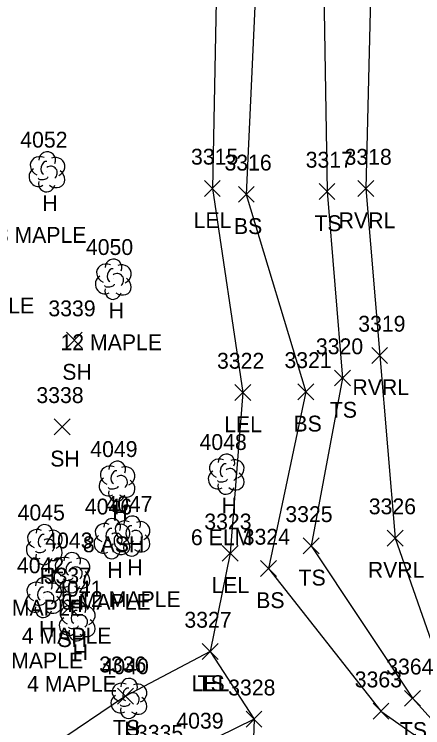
# Model space of a CAD drawing. Extents: x 1461855 to 1464118, y 556196 to 557441.
# Drawn here: x 1462006.8 to 1462058.2, y 556619.2 to 556709.1 of the extents above; entities that cross this region are included whole.
import ezdxf

# ---------------------------------------------------------------- set-up
doc = ezdxf.new("R2010")
doc.units = 0
for name, color, linetype in [('L_A', 7, 'Continuous'), ('L_C', 7, 'Continuous'), ('L_I', 7, 'Continuous'), ('L_TIC', 7, 'Continuous'), ('LARO', 7, 'Continuous'), ('LAWE', 7, 'Continuous'), ('LELB', 7, 'Continuous'), ('LTD', 7, 'Continuous')]:
    doc.layers.add(name, color=color, linetype=linetype)

msp = doc.modelspace()

# ---------------------------------------------------------------- linework, layer by layer
at = {"layer": 'L_TIC'}
for points in [[(1462030.75, 556686.131), (1462032.75, 556688.131)], [(1462032.75, 556686.131), (1462030.75, 556688.131)], [(1462035.024, 556685.385), (1462037.024, 556687.385)], [(1462037.024, 556685.385), (1462035.024, 556687.385)], [(1462045.194, 556685.747), (1462047.194, 556687.747)], [(1462047.194, 556685.747), (1462045.194, 556687.747)], [(1462045.194, 556685.747), (1462047.194, 556687.747)], [(1462047.194, 556685.747), (1462045.194, 556687.747)], [(1462050.091, 556686.112), (1462052.091, 556688.112)], [(1462052.091, 556686.112), (1462050.091, 556688.112)], [(1462013.361, 556667.016), (1462015.361, 556669.016)], [(1462015.361, 556667.016), (1462013.361, 556669.016)], [(1462051.825, 556665.076), (1462053.825, 556667.076)], [(1462053.825, 556665.076), (1462051.825, 556667.076)], [(1462047.138, 556662.233), (1462049.138, 556664.233)], [(1462049.138, 556662.233), (1462047.138, 556664.233)], [(1462034.594, 556660.411), (1462036.594, 556662.411)], [(1462036.594, 556660.411), (1462034.594, 556662.411)], [(1462042.522, 556660.49), (1462044.522, 556662.49)], [(1462044.522, 556660.49), (1462042.522, 556662.49)], [(1462011.842, 556656.082), (1462013.842, 556658.082)], [(1462013.842, 556656.082), (1462011.842, 556658.082)], [(1462053.764, 556642.062), (1462055.764, 556644.062)], [(1462055.764, 556642.062), (1462053.764, 556644.062)], [(1462043.201, 556641.081), (1462045.201, 556643.081)], [(1462045.201, 556641.081), (1462043.201, 556643.081)], [(1462032.996, 556640.147), (1462034.996, 556642.147)], [(1462034.996, 556640.147), (1462032.996, 556642.147)], [(1462037.833, 556638.233), (1462039.833, 556640.233)], [(1462039.833, 556638.233), (1462037.833, 556640.233)], [(1462012.766, 556633.331), (1462014.766, 556635.331)], [(1462014.766, 556633.331), (1462012.766, 556635.331)], [(1462030.483, 556627.768), (1462032.483, 556629.768)], [(1462032.483, 556627.768), (1462030.483, 556629.768)], [(1462030.483, 556627.768), (1462032.483, 556629.768)], [(1462032.483, 556627.768), (1462030.483, 556629.768)], [(1462019.803, 556622.137), (1462021.803, 556624.137)], [(1462021.803, 556622.137), (1462019.803, 556624.137)], [(1462055.957, 556621.87), (1462057.957, 556623.87)], [(1462057.957, 556621.87), (1462055.957, 556623.87)], [(1462051.988, 556620.249), (1462053.988, 556622.249)], [(1462053.988, 556620.249), (1462051.988, 556622.249)], [(1462036, 556619.231), (1462038, 556621.231)], [(1462038, 556619.231), (1462036, 556621.231)], [(1462036, 556619.231), (1462038, 556621.231)], [(1462038, 556619.231), (1462036, 556621.231)]]:
    msp.add_lwpolyline(points, dxfattribs=at)
at = {"layer": 'LARO'}
msp.add_lwpolyline([(1462028.293, 556804.845), (1462029.856, 556786.264), (1462034.967, 556768.458), (1462036.472, 556762.979), (1462033.427, 556748.898), (1462029.252, 556744.558), (1462032.364, 556727.057), (1462032.403, 556719.386), (1462031.75, 556687.131), (1462035.594, 556661.411), (1462033.996, 556641.147), (1462031.483, 556628.768), (1462037, 556620.231), (1462036.776, 556613.093), (1462055.688, 556606.979), (1462067.548, 556606.631), (1462078.525, 556595.396), (1462093.66, 556580.158), (1462100.331, 556564.645), (1462103.465, 556550.963), (1462104.582, 556534.352), (1462113.504, 556526.22)], dxfattribs=at)
at = {"layer": 'LAWE'}
msp.add_lwpolyline([(1462035.855, 556809.685), (1462040.285, 556805.29), (1462046.447, 556786.582), (1462047.954, 556769.867), (1462051.587, 556748.694), (1462051.929, 556721.581), (1462051.091, 556687.112), (1462052.825, 556666.076), (1462054.764, 556643.062), (1462061.562, 556623.629), (1462070.818, 556617.59), (1462084.777, 556608.704), (1462105.974, 556601.343), (1462119.177, 556579.727), (1462124.613, 556564.474), (1462124.915, 556535.352)], dxfattribs=at)
at = {"layer": 'LELB'}
for points in [[(1462040.285, 556805.29), (1462040.375, 556785.854), (1462042.823, 556769.757), (1462047.844, 556748.135), (1462045.64, 556722.171), (1462046.194, 556686.747)], [(1462033.427, 556748.898), (1462037.255, 556728.002), (1462037.528, 556719.234), (1462036.024, 556686.385), (1462043.522, 556661.49), (1462038.833, 556639.233), (1462052.988, 556621.249), (1462067.983, 556610.68)], [(1462046.194, 556686.747), (1462048.138, 556663.233), (1462044.201, 556642.081), (1462056.957, 556622.87), (1462067.983, 556610.68), (1462080.94, 556602.236), (1462101.79, 556592.319), (1462108.001, 556571.986), (1462115.176, 556557.681), (1462103.465, 556550.963), (1462124.915, 556535.352)], [(1462031.483, 556628.768), (1462020.803, 556623.137), (1462002.36, 556610.719)], [(1462037, 556620.231), (1462025.387, 556614.515), (1462007.069, 556609.236), (1462003.91, 556604.783)]]:
    msp.add_lwpolyline(points, dxfattribs=at)
at = {"layer": 'LTD'}
for p, q in [((1462010.891, 556689.273), (1462010.891, 556689.273)), ((1462010.891, 556689.273), (1462010.891, 556689.273)), ((1462019.248, 556675.743), (1462019.248, 556675.743)), ((1462019.248, 556675.743), (1462019.248, 556675.743)), ((1462033.473, 556651.168), (1462033.473, 556651.168)), ((1462033.473, 556651.168), (1462033.473, 556651.168)), ((1462019.721, 556650.279), (1462019.721, 556650.279)), ((1462019.721, 556650.279), (1462019.721, 556650.279)), ((1462021.603, 556643.369), (1462021.603, 556643.369)), ((1462021.603, 556643.369), (1462021.603, 556643.369)), ((1462019.081, 556643.036), (1462019.081, 556643.036)), ((1462019.081, 556643.036), (1462019.081, 556643.036)), ((1462010.561, 556642.282), (1462010.561, 556642.282)), ((1462010.561, 556642.282), (1462010.561, 556642.282)), ((1462014.04, 556638.764), (1462014.04, 556638.764)), ((1462014.04, 556638.764), (1462014.04, 556638.764)), ((1462010.473, 556635.628), (1462010.473, 556635.628)), ((1462010.473, 556635.628), (1462010.473, 556635.628)), ((1462014.709, 556632.69), (1462014.709, 556632.69)), ((1462014.709, 556632.69), (1462014.709, 556632.69)), ((1462021.217, 556622.908), (1462021.217, 556622.908)), ((1462021.217, 556622.908), (1462021.217, 556622.908))]:
    msp.add_line(p, q, dxfattribs=at)
for centre in [(1462010.938, 556690.707), (1462019.294, 556677.177), (1462033.52, 556652.602), (1462019.768, 556651.713), (1462019.128, 556644.47), (1462021.65, 556644.803), (1462010.608, 556643.716), (1462014.087, 556640.198), (1462010.52, 556637.061), (1462014.756, 556634.124), (1462021.264, 556624.342)]:
    msp.add_arc(centre, 1.047, 335.52715, 180.95627, dxfattribs=at)
for centre, major_axis, ratio, start_param, end_param in [((1462010.099, 556689.94), (1.21, -0.512), 0.895232, 1.570796, 4.712389), ((1462011.933, 556689.857), (-1.141, -0.483), 0.949671, 1.570796, 4.712389), ((1462010.683, 556689.731), (-0.208, -0.792), 0.645439, 3.141593, 6.283185), ((1462011.391, 556689.106), (-0.5, 0.667), 0.989748, 3.141593, 6.283185), ((1462009.808, 556688.564), (0.584, -1.042), 0.959034, 3.141593, 6.283185), ((1462011.891, 556688.44), (-1.09, 0.792), 0.841452, 1.570796, 4.712389), ((1462010.433, 556688.523), (-0.625, -0.083), 0.423636, 0, 3.141593), ((1462010.891, 556687.773), (0.265, 1.061), 0.942809, 1.570796, 4.712389), ((1462018.456, 556676.409), (1.21, -0.512), 0.895232, 1.570796, 4.712389), ((1462020.289, 556676.326), (-1.141, -0.483), 0.949671, 1.570796, 4.712389), ((1462019.039, 556676.201), (-0.208, -0.792), 0.645439, 3.141593, 6.283185), ((1462018.164, 556675.034), (0.584, -1.042), 0.959034, 3.141593, 6.283185), ((1462019.748, 556675.576), (-0.5, 0.667), 0.989748, 3.141593, 6.283185), ((1462020.248, 556674.91), (-1.09, 0.792), 0.841452, 1.570796, 4.712389), ((1462018.789, 556674.993), (-0.625, -0.083), 0.423636, 0, 3.141593), ((1462019.248, 556674.243), (0.265, 1.061), 0.942809, 1.570796, 4.712389), ((1462032.681, 556651.834), (1.21, -0.512), 0.895232, 1.570796, 4.712389), ((1462018.93, 556650.946), (1.21, -0.512), 0.895232, 1.570796, 4.712389), ((1462033.264, 556651.626), (-0.208, -0.792), 0.645439, 3.141593, 6.283185), ((1462034.514, 556651.751), (-1.141, -0.483), 0.949671, 1.570796, 4.712389), ((1462019.513, 556650.737), (-0.208, -0.792), 0.645439, 3.141593, 6.283185), ((1462020.763, 556650.863), (-1.141, -0.483), 0.949671, 1.570796, 4.712389), ((1462032.39, 556650.459), (0.584, -1.042), 0.959034, 3.141593, 6.283185), ((1462033.973, 556651.001), (-0.5, 0.667), 0.989748, 3.141593, 6.283185), ((1462018.638, 556649.57), (0.584, -1.042), 0.959034, 3.141593, 6.283185), ((1462020.221, 556650.112), (-0.5, 0.667), 0.989748, 3.141593, 6.283185), ((1462033.015, 556650.418), (-0.625, -0.083), 0.423636, 0, 3.141593), ((1462034.473, 556650.335), (-1.09, 0.792), 0.841452, 1.570796, 4.712389), ((1462019.263, 556649.529), (-0.625, -0.083), 0.423636, 0, 3.141593), ((1462020.722, 556649.446), (-1.09, 0.792), 0.841452, 1.570796, 4.712389), ((1462033.473, 556649.668), (0.265, 1.061), 0.942809, 1.570796, 4.712389), ((1462019.722, 556648.779), (0.265, 1.061), 0.942809, 1.570796, 4.712389), ((1462018.289, 556643.703), (1.21, -0.512), 0.895232, 1.570796, 4.712389), ((1462020.812, 556644.036), (1.21, -0.512), 0.895232, 1.570796, 4.712389), ((1462022.645, 556643.953), (-1.141, -0.483), 0.949671, 1.570796, 4.712389), ((1462009.769, 556642.948), (1.21, -0.512), 0.895232, 1.570796, 4.712389), ((1462011.603, 556642.865), (-1.141, -0.483), 0.949671, 1.570796, 4.712389), ((1462018.872, 556643.494), (-0.208, -0.792), 0.645439, 3.141593, 6.283185), ((1462020.122, 556643.62), (-1.141, -0.483), 0.949671, 1.570796, 4.712389), ((1462021.395, 556643.828), (-0.208, -0.792), 0.645439, 3.141593, 6.283185), ((1462010.353, 556642.74), (-0.208, -0.792), 0.645439, 3.141593, 6.283185), ((1462017.998, 556642.328), (0.584, -1.042), 0.959034, 3.141593, 6.283185), ((1462019.581, 556642.87), (-0.5, 0.667), 0.989748, 3.141593, 6.283185), ((1462020.52, 556642.661), (0.584, -1.042), 0.959034, 3.141593, 6.283185), ((1462022.103, 556643.203), (-0.5, 0.667), 0.989748, 3.141593, 6.283185), ((1462022.604, 556642.536), (-1.09, 0.792), 0.841452, 1.570796, 4.712389), ((1462009.478, 556641.573), (0.584, -1.042), 0.959034, 3.141593, 6.283185), ((1462011.061, 556642.115), (-0.5, 0.667), 0.989748, 3.141593, 6.283185), ((1462018.623, 556642.286), (-0.625, -0.083), 0.423636, 0, 3.141593), ((1462020.081, 556642.203), (-1.09, 0.792), 0.841452, 1.570796, 4.712389), ((1462021.145, 556642.619), (-0.625, -0.083), 0.423636, 0, 3.141593), ((1462010.103, 556641.532), (-0.625, -0.083), 0.423636, 0, 3.141593), ((1462011.561, 556641.449), (-1.09, 0.792), 0.841452, 1.570796, 4.712389), ((1462019.081, 556641.536), (0.265, 1.061), 0.942809, 1.570796, 4.712389), ((1462021.604, 556641.869), (0.265, 1.061), 0.942809, 1.570796, 4.712389), ((1462010.561, 556640.782), (0.265, 1.061), 0.942809, 1.570796, 4.712389), ((1462013.249, 556639.43), (1.21, -0.512), 0.895232, 1.570796, 4.712389), ((1462015.082, 556639.347), (-1.141, -0.483), 0.949671, 1.570796, 4.712389), ((1462013.832, 556639.222), (-0.208, -0.792), 0.645439, 3.141593, 6.283185), ((1462012.957, 556638.055), (0.584, -1.042), 0.959034, 3.141593, 6.283185), ((1462014.54, 556638.597), (-0.5, 0.667), 0.989748, 3.141593, 6.283185), ((1462015.04, 556637.931), (-1.09, 0.792), 0.841452, 1.570796, 4.712389), ((1462013.582, 556638.014), (-0.625, -0.083), 0.423636, 0, 3.141593), ((1462009.681, 556636.294), (1.21, -0.512), 0.895232, 1.570796, 4.712389), ((1462011.515, 556636.211), (-1.141, -0.483), 0.949671, 1.570796, 4.712389), ((1462014.041, 556637.264), (0.265, 1.061), 0.942809, 1.570796, 4.712389), ((1462010.265, 556636.086), (-0.208, -0.792), 0.645439, 3.141593, 6.283185), ((1462010.973, 556635.461), (-0.5, 0.667), 0.989748, 3.141593, 6.283185), ((1462009.39, 556634.919), (0.584, -1.042), 0.959034, 3.141593, 6.283185), ((1462011.473, 556634.794), (-1.09, 0.792), 0.841452, 1.570796, 4.712389), ((1462010.473, 556634.128), (0.265, 1.061), 0.942809, 1.570796, 4.712389), ((1462010.015, 556634.877), (-0.625, -0.083), 0.423636, 0, 3.141593), ((1462013.917, 556633.357), (1.21, -0.512), 0.895232, 1.570796, 4.712389), ((1462015.751, 556633.274), (-1.141, -0.483), 0.949671, 1.570796, 4.712389), ((1462014.501, 556633.149), (-0.208, -0.792), 0.645439, 3.141593, 6.283185), ((1462015.209, 556632.524), (-0.5, 0.667), 0.989748, 3.141593, 6.283185), ((1462013.626, 556631.982), (0.584, -1.042), 0.959034, 3.141593, 6.283185), ((1462015.709, 556631.857), (-1.09, 0.792), 0.841452, 1.570796, 4.712389), ((1462014.251, 556631.94), (-0.625, -0.083), 0.423636, 0, 3.141593), ((1462014.71, 556631.19), (0.265, 1.061), 0.942809, 1.570796, 4.712389), ((1462020.425, 556623.574), (1.21, -0.512), 0.895232, 1.570796, 4.712389), ((1462022.258, 556623.491), (-1.141, -0.483), 0.949671, 1.570796, 4.712389), ((1462021.008, 556623.366), (-0.208, -0.792), 0.645439, 3.141593, 6.283185), ((1462021.717, 556622.741), (-0.5, 0.667), 0.989748, 3.141593, 6.283185), ((1462020.134, 556622.199), (0.584, -1.042), 0.959034, 3.141593, 6.283185), ((1462022.217, 556622.074), (-1.09, 0.792), 0.841452, 1.570796, 4.712389), ((1462020.759, 556622.158), (-0.625, -0.083), 0.423636, 0, 3.141593), ((1462021.217, 556621.408), (0.265, 1.061), 0.942809, 1.570796, 4.712389)]:
    msp.add_ellipse(centre, major_axis=major_axis, ratio=ratio, start_param=start_param, end_param=end_param, dxfattribs=at)

# ---------------------------------------------------------------- texts
at = {"layer": 'L_A'}
for s, p in [('H', (1462010.324, 556684.273)), ('LEL', (1462029.388, 556682.131)), ('TS', (1462044.604, 556681.747)), ('TS', (1462044.604, 556681.747)), ('RVRL', (1462047.658, 556682.112)), ('BS', (1462034.465, 556681.385)), ('H', (1462018.681, 556670.743)), ('SH', (1462012.849, 556663.016)), ('RVRL', (1462049.391, 556661.076)), ('TS', (1462046.548, 556658.233)), ('LEL', (1462033.232, 556656.411)), ('BS', (1462041.963, 556656.49)), ('SH', (1462011.33, 556652.082)), ('H', (1462032.906, 556646.168)), ('H', (1462019.154, 556645.279)), ('H', (1462018.514, 556638.036)), ('H', (1462021.036, 556638.369)), ('RVRL', (1462051.33, 556638.062)), ('H', (1462009.994, 556637.282)), ('TS', (1462042.611, 556637.081)), ('LEL', (1462031.634, 556636.147)), ('BS', (1462037.274, 556634.233)), ('H', (1462013.473, 556633.764)), ('H', (1462009.906, 556630.628)), ('SH', (1462012.254, 556629.331)), ('H', (1462014.142, 556627.69)), ('LEL', (1462029.121, 556623.768)), ('TS', (1462029.892, 556623.768)), ('TS', (1462019.213, 556618.137)), ('H', (1462020.65, 556617.908)), ('TS', (1462055.366, 556617.87))]:
    msp.add_text(s, height=2, dxfattribs=at).set_placement(p)
at = {"layer": 'L_C'}
for s, p in [('8 MAPLE', (1462004.592, 556680.273)), ('10 MAPLE', (1461996.528, 556671.378)), ('12 MAPLE', (1462012.618, 556666.743)), ('6 ELM', (1462029.048, 556642.168)), ('8 ASH', (1462015.438, 556641.279)), ('12 MAPLE', (1462014.973, 556634.369)), ('8 MAPLE', (1462004.262, 556633.282)), ('6 MAPLE', (1462012.687, 556634.036)), ('4 MAPLE', (1462007.741, 556629.764)), ('4 MAPLE', (1462004.174, 556626.628)), ('4 MAPLE', (1462008.41, 556623.69))]:
    msp.add_text(s, height=2, dxfattribs=at).set_placement(p)
at = {"layer": 'L_I'}
for s, p in [('4052', (1462007.553, 556692.273)), ('3315', (1462029.057, 556690.131)), ('3318', (1462048.398, 556690.112)), ('3316', (1462033.276, 556689.385)), ('3317', (1462043.501, 556689.747)), ('3317', (1462043.501, 556689.747)), ('4050', (1462015.822, 556678.743)), ('3339', (1462011.093, 556671.016)), ('3319', (1462050.124, 556669.076)), ('3320', (1462044.792, 556666.233)), ('3322', (1462032.334, 556664.411)), ('3321', (1462040.829, 556664.49)), ('3338', (1462009.582, 556660.082)), ('4048', (1462030.134, 556654.168)), ('4049', (1462016.375, 556653.279)), ('4046', (1462015.687, 556646.036)), ('4047', (1462018.265, 556646.369)), ('3326', (1462051.449, 556646.062)), ('4045', (1462007.223, 556645.282)), ('3325', (1462040.941, 556645.081)), ('3323', (1462030.736, 556644.147)), ('3324', (1462035.573, 556642.233)), ('4043', (1462010.702, 556641.764)), ('4042', (1462007.135, 556638.628)), ('3337', (1462010.506, 556637.331)), ('4041', (1462011.938, 556635.69)), ('3327', (1462028.223, 556631.768)), ('3327', (1462028.223, 556631.768)), ('3336', (1462017.488, 556626.137)), ('4040', (1462017.792, 556625.908)), ('3364', (1462053.649, 556625.87)), ('3363', (1462049.681, 556624.249)), ('3328', (1462033.74, 556623.231)), ('3328', (1462033.74, 556623.231)), ('4039', (1462027.212, 556619.047)), ('3335', (1462022.127, 556617.515))]:
    msp.add_text(s, height=2, dxfattribs=at).set_placement(p)

doc.saveas('drawing.dxf')
